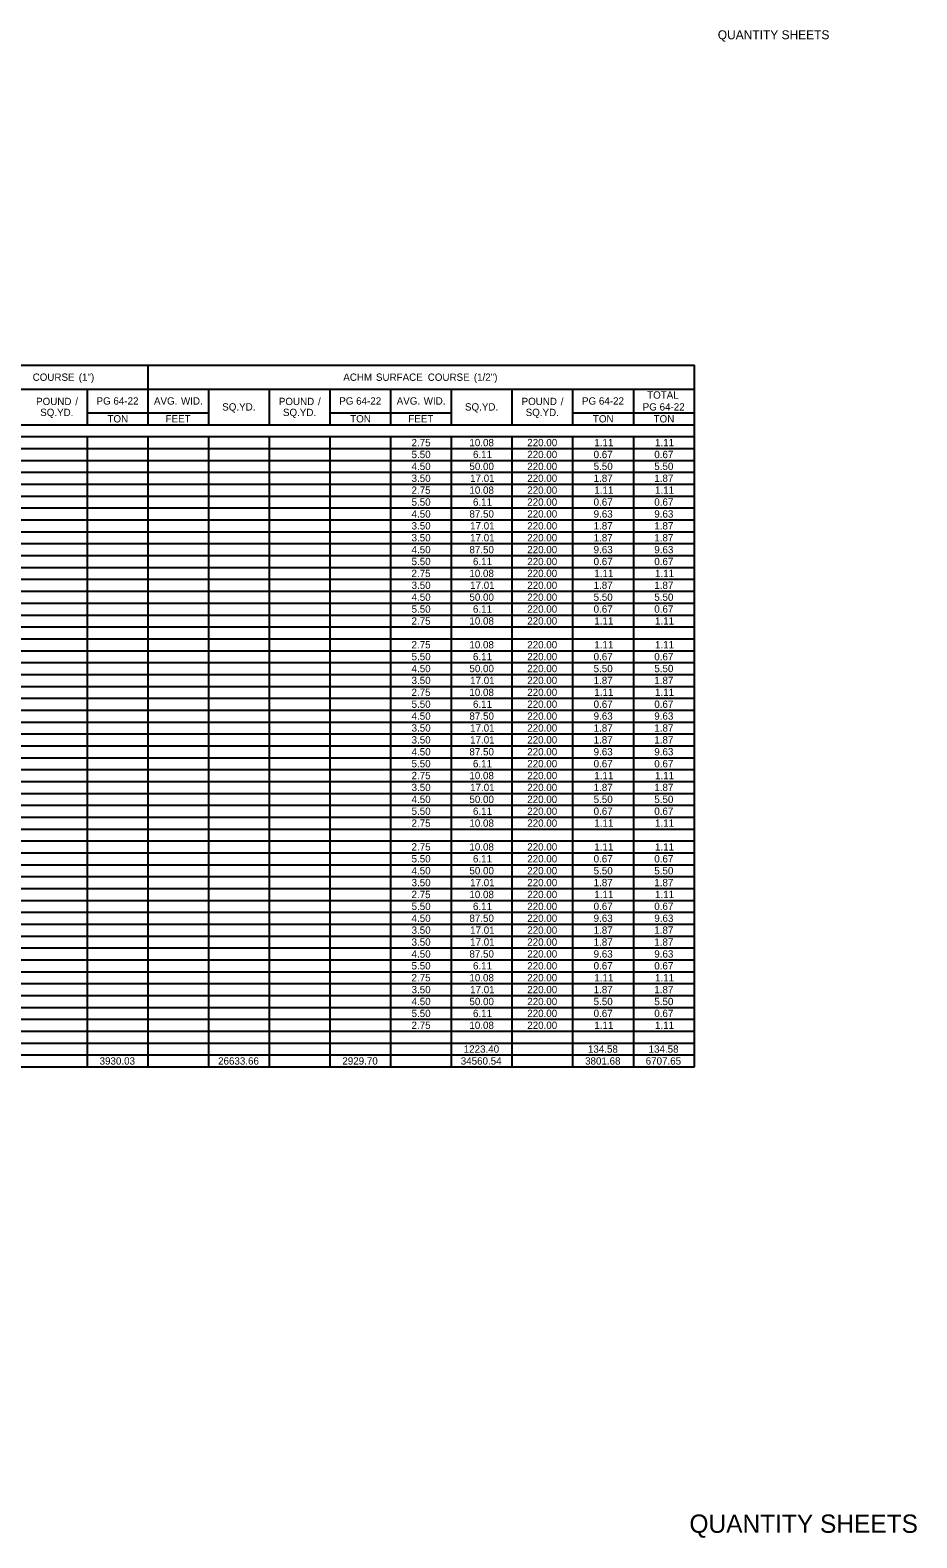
# Model space of a CAD drawing. Extents: x 977434 to 989596, y 1525697 to 1528336.
# Drawn here: x 985434 to 986015, y 1527332 to 1528321 of the extents above; entities that cross this region are included whole.
import ezdxf

# ---------------------------------------------------------------- set-up
doc = ezdxf.new("R2010")
doc.units = 0
for name, color, linetype in [('Default', 7, 'Continuous'), ('R_Border', 7, 'Continuous'), ('R_Border Prem', 7, 'Continuous')]:
    doc.layers.add(name, color=color, linetype=linetype)

msp = doc.modelspace()

# ---------------------------------------------------------------- linework, layer by layer
at = {"layer": 'Default'}
for p, q in [((984511.57, 1528101.06), (985869.55, 1528101.06)), ((985511.53, 1528085.46), (985511.53, 1528101.06)), ((985511.53, 1528062.06), (985511.53, 1528101.06)), ((985869.55, 1527656.46), (985869.55, 1528101.06)), ((985869.55, 1527640.86), (985869.55, 1528101.06)), ((984835.27, 1528085.46), (985869.55, 1528085.46)), ((985471.75, 1528062.06), (985471.75, 1528085.46)), ((985551.31, 1528085.46), (985591.09, 1528085.46)), ((985551.31, 1528062.06), (985551.31, 1528085.46)), ((985591.09, 1528062.06), (985591.09, 1528085.46)), ((985630.87, 1528062.06), (985630.87, 1528085.46)), ((985670.65, 1528062.06), (985670.65, 1528085.46)), ((985710.43, 1528085.46), (985750.21, 1528085.46)), ((985710.43, 1528062.06), (985710.43, 1528085.46)), ((985750.21, 1528062.06), (985750.21, 1528085.46)), ((985789.99, 1528062.06), (985789.99, 1528085.46)), ((985829.77, 1528062.06), (985829.77, 1528085.46)), ((984511.57, 1528062.06), (985869.55, 1528062.06)), ((985392.19, 1528062.06), (985551.31, 1528062.06)), ((985471.75, 1528069.86), (985551.31, 1528069.86)), ((985511.53, 1528062.06), (985511.53, 1528069.86)), ((985551.31, 1528062.06), (985551.31, 1528069.86)), ((985551.31, 1528062.06), (985710.43, 1528062.06)), ((985630.87, 1528069.86), (985710.43, 1528069.86)), ((985670.65, 1528062.06), (985670.65, 1528069.86)), ((985710.43, 1528062.06), (985710.43, 1528069.86)), ((985710.43, 1528062.06), (985869.55, 1528062.06)), ((985789.99, 1528069.86), (985869.55, 1528069.86)), ((984511.57, 1528054.26), (985869.55, 1528054.26)), ((985471.75, 1527640.86), (985471.75, 1528054.26)), ((985471.75, 1527640.86), (985471.75, 1528054.26)), ((985511.53, 1527640.86), (985511.53, 1528054.26)), ((985511.53, 1527640.86), (985511.53, 1528054.26)), ((985551.31, 1527640.86), (985551.31, 1528054.26)), ((985551.31, 1527640.86), (985551.31, 1528054.26)), ((985591.09, 1527664.26), (985591.09, 1528054.26)), ((985591.09, 1527640.86), (985591.09, 1528054.26)), ((985630.87, 1527640.86), (985630.87, 1528054.26)), ((985630.87, 1527640.86), (985630.87, 1528054.26)), ((985670.65, 1527656.46), (985670.65, 1528054.26)), ((985670.65, 1527640.86), (985670.65, 1528054.26)), ((985710.43, 1527640.86), (985710.43, 1528054.26)), ((985710.43, 1527640.86), (985710.43, 1528054.26)), ((985750.21, 1527640.86), (985750.21, 1528054.26)), ((985750.21, 1527640.86), (985750.21, 1528054.26)), ((985789.99, 1527640.86), (985789.99, 1528054.26)), ((985789.99, 1527640.86), (985789.99, 1528054.26)), ((985829.77, 1527640.86), (985829.77, 1528054.26)), ((985829.77, 1527640.86), (985829.77, 1528054.26)), ((984511.57, 1528046.46), (985869.55, 1528046.46)), ((984511.57, 1528038.66), (985869.55, 1528038.66)), ((984511.57, 1528030.86), (985869.55, 1528030.86)), ((984511.57, 1528023.06), (985869.55, 1528023.06)), ((984511.57, 1528015.26), (985869.55, 1528015.26)), ((984511.57, 1528007.46), (985869.55, 1528007.46)), ((984511.57, 1527999.66), (985869.55, 1527999.66)), ((984511.57, 1527991.86), (985869.55, 1527991.86)), ((984511.57, 1527984.06), (985869.55, 1527984.06)), ((984511.57, 1527976.26), (985869.55, 1527976.26)), ((984511.57, 1527968.46), (985869.55, 1527968.46)), ((984511.57, 1527960.66), (985869.55, 1527960.66)), ((984511.57, 1527952.86), (985869.55, 1527952.86)), ((984511.57, 1527945.06), (985869.55, 1527945.06)), ((984511.57, 1527937.26), (985869.55, 1527937.26)), ((984511.57, 1527929.46), (985869.55, 1527929.46)), ((984511.57, 1527921.66), (985869.55, 1527921.66)), ((984511.57, 1527913.86), (985869.55, 1527913.86)), ((984511.57, 1527906.06), (985869.55, 1527906.06)), ((984511.57, 1527898.26), (985869.55, 1527898.26)), ((984511.57, 1527890.46), (985869.55, 1527890.46)), ((984511.57, 1527882.66), (985869.55, 1527882.66)), ((984511.57, 1527874.86), (985869.55, 1527874.86)), ((984511.57, 1527867.06), (985869.55, 1527867.06)), ((984511.57, 1527859.26), (985869.55, 1527859.26)), ((984511.57, 1527851.46), (985869.55, 1527851.46)), ((984511.57, 1527843.66), (985869.55, 1527843.66)), ((984511.57, 1527835.86), (985869.55, 1527835.86)), ((984511.57, 1527828.06), (985869.55, 1527828.06)), ((984511.57, 1527820.26), (985869.55, 1527820.26)), ((984511.57, 1527812.46), (985869.55, 1527812.46)), ((984511.57, 1527804.66), (985869.55, 1527804.66)), ((984511.57, 1527796.86), (985869.55, 1527796.86)), ((984511.57, 1527789.06), (985869.55, 1527789.06)), ((984511.57, 1527781.26), (985869.55, 1527781.26)), ((984511.57, 1527773.46), (985869.55, 1527773.46)), ((984511.57, 1527765.66), (985869.55, 1527765.66)), ((984511.57, 1527757.86), (985869.55, 1527757.86)), ((984511.57, 1527750.06), (985869.55, 1527750.06)), ((984511.57, 1527742.26), (985869.55, 1527742.26)), ((984511.57, 1527734.46), (985869.55, 1527734.46)), ((984511.57, 1527726.66), (985869.55, 1527726.66)), ((984511.57, 1527718.86), (985869.55, 1527718.86)), ((984511.57, 1527711.06), (985869.55, 1527711.06)), ((984511.57, 1527703.26), (985869.55, 1527703.26)), ((984511.57, 1527695.46), (985869.55, 1527695.46)), ((984511.57, 1527687.66), (985869.55, 1527687.66)), ((984511.57, 1527679.86), (985869.55, 1527679.86)), ((984511.57, 1527672.06), (985869.55, 1527672.06)), ((984511.57, 1527664.26), (985869.55, 1527664.26)), ((984511.57, 1527656.46), (985869.55, 1527656.46)), ((984511.57, 1527648.66), (985869.55, 1527648.66)), ((985591.09, 1527640.86), (985591.09, 1527656.46)), ((985630.87, 1527656.46), (985670.65, 1527656.46)), ((985670.65, 1527656.46), (985829.77, 1527656.46)), ((985670.65, 1527640.86), (985670.65, 1527648.66)), ((985829.77, 1527656.46), (985869.55, 1527656.46)), ((985869.55, 1527640.86), (985869.55, 1527648.66)), ((984511.57, 1527640.86), (985869.55, 1527640.86))]:
    msp.add_line(p, q, dxfattribs=at)

# ---------------------------------------------------------------- texts
for s, p in [(' COURSE', (985434.01, 1528090.86)), (' (1")', (985464.23, 1528090.86)), ('ACHM', (985639.4, 1528090.86)), (' SURFACE', (985659.04, 1528090.86)), (' COURSE', (985692.99, 1528090.86)), (' (1/2")', (985723.21, 1528090.86)), ('TOTAL', (985838.59, 1528079.16)), ('POUND', (985438.05, 1528074.96)), ('SQ.YD.', (985440.73, 1528067.76)), (' /', (985461.94, 1528074.96)), ('PG', (985477.66, 1528075.26)), (' 64-22', (985486.95, 1528075.26)), ('AVG.', (985515.3, 1528075.26)), (' WID.', (985531.24, 1528075.26)), ('SQ.YD.', (985560.07, 1528071.36)), ('POUND', (985597.17, 1528074.96)), ('SQ.YD.', (985599.85, 1528067.76)), (' /', (985621.06, 1528074.96)), ('PG', (985636.78, 1528075.26)), (' 64-22', (985646.07, 1528075.26)), ('AVG.', (985674.42, 1528075.26)), (' WID.', (985690.36, 1528075.26)), ('SQ.YD.', (985719.19, 1528071.36)), ('POUND', (985756.29, 1528074.96)), ('SQ.YD.', (985758.97, 1528067.76)), (' /', (985780.18, 1528074.96)), ('PG', (985795.9, 1528075.26)), (' 64-22', (985805.19, 1528075.26)), ('PG', (985835.68, 1528071.36)), (' 64-22', (985844.97, 1528071.36)), ('TON', (985484.83, 1528063.56)), ('FEET', (985522.92, 1528063.56)), ('TON', (985643.95, 1528063.56)), ('FEET', (985682.04, 1528063.56)), ('TON', (985803.07, 1528063.56)), ('TON', (985842.85, 1528063.56)), ('2.75', (985684.15, 1528047.96)), ('10.08', (985722.08, 1528047.96)), ('220.00', (985760.01, 1528047.96)), ('1.11', (985803.98, 1528047.96)), ('1.11', (985843.76, 1528047.96)), ('5.50', (985684.18, 1528040.16)), ('6.11', (985724.42, 1528040.16)), ('220.00', (985760.01, 1528040.16)), ('0.67', (985803.51, 1528040.16)), ('0.67', (985843.29, 1528040.16)), ('4.50', (985684.18, 1528032.36)), ('50.00', (985722.1, 1528032.36)), ('220.00', (985760.01, 1528032.36)), ('5.50', (985803.52, 1528032.36)), ('5.50', (985843.3, 1528032.36)), ('3.50', (985684.18, 1528024.56)), ('17.01', (985722.55, 1528024.56)), ('220.00', (985760.01, 1528024.56)), ('1.87', (985803.51, 1528024.56)), ('1.87', (985843.29, 1528024.56)), ('5.50', (985684.18, 1528008.96)), ('2.75', (985684.15, 1528016.76)), ('10.08', (985722.08, 1528016.76)), ('6.11', (985724.42, 1528008.96)), ('220.00', (985760.01, 1528016.76)), ('220.00', (985760.01, 1528008.96)), ('0.67', (985803.51, 1528008.96)), ('1.11', (985803.98, 1528016.76)), ('0.67', (985843.29, 1528008.96)), ('1.11', (985843.76, 1528016.76)), ('4.50', (985684.18, 1528001.16)), ('87.50', (985722.1, 1528001.16)), ('220.00', (985760.01, 1528001.16)), ('9.63', (985803.51, 1528001.16)), ('9.63', (985843.29, 1528001.16)), ('3.50', (985684.18, 1527993.36)), ('17.01', (985722.55, 1527993.36)), ('220.00', (985760.01, 1527993.36)), ('1.87', (985803.51, 1527993.36)), ('1.87', (985843.29, 1527993.36)), ('3.50', (985684.18, 1527985.56)), ('17.01', (985722.55, 1527985.56)), ('220.00', (985760.01, 1527985.56)), ('1.87', (985803.51, 1527985.56)), ('1.87', (985843.29, 1527985.56)), ('4.50', (985684.18, 1527977.76)), ('5.50', (985684.18, 1527969.96)), ('87.50', (985722.1, 1527977.76)), ('6.11', (985724.42, 1527969.96)), ('220.00', (985760.01, 1527977.76)), ('220.00', (985760.01, 1527969.96)), ('0.67', (985803.51, 1527969.96)), ('9.63', (985803.51, 1527977.76)), ('0.67', (985843.29, 1527969.96)), ('9.63', (985843.29, 1527977.76)), ('2.75', (985684.15, 1527962.16)), ('10.08', (985722.08, 1527962.16)), ('220.00', (985760.01, 1527962.16)), ('1.11', (985803.98, 1527962.16)), ('1.11', (985843.76, 1527962.16)), ('3.50', (985684.18, 1527954.36)), ('17.01', (985722.55, 1527954.36)), ('220.00', (985760.01, 1527954.36)), ('1.87', (985803.51, 1527954.36)), ('1.87', (985843.29, 1527954.36)), ('4.50', (985684.18, 1527946.56)), ('5.50', (985684.18, 1527938.76)), ('50.00', (985722.1, 1527946.56)), ('6.11', (985724.42, 1527938.76)), ('220.00', (985760.01, 1527946.56)), ('220.00', (985760.01, 1527938.76)), ('0.67', (985803.51, 1527938.76)), ('5.50', (985803.52, 1527946.56)), ('0.67', (985843.29, 1527938.76)), ('5.50', (985843.3, 1527946.56)), ('2.75', (985684.15, 1527930.96)), ('10.08', (985722.08, 1527930.96)), ('220.00', (985760.01, 1527930.96)), ('1.11', (985803.98, 1527930.96)), ('1.11', (985843.76, 1527930.96)), ('2.75', (985684.15, 1527915.36)), ('10.08', (985722.08, 1527915.36)), ('220.00', (985760.01, 1527915.36)), ('1.11', (985803.98, 1527915.36)), ('1.11', (985843.76, 1527915.36)), ('4.50', (985684.18, 1527899.76)), ('5.50', (985684.18, 1527907.56)), ('50.00', (985722.1, 1527899.76)), ('6.11', (985724.42, 1527907.56)), ('220.00', (985760.01, 1527907.56)), ('220.00', (985760.01, 1527899.76)), ('0.67', (985803.51, 1527907.56)), ('5.50', (985803.52, 1527899.76)), ('0.67', (985843.29, 1527907.56)), ('5.50', (985843.3, 1527899.76)), ('3.50', (985684.18, 1527891.96)), ('17.01', (985722.55, 1527891.96)), ('220.00', (985760.01, 1527891.96)), ('1.87', (985803.51, 1527891.96)), ('1.87', (985843.29, 1527891.96)), ('2.75', (985684.15, 1527884.16)), ('10.08', (985722.08, 1527884.16)), ('220.00', (985760.01, 1527884.16)), ('1.11', (985803.98, 1527884.16)), ('1.11', (985843.76, 1527884.16)), ('5.50', (985684.18, 1527876.36)), ('6.11', (985724.42, 1527876.36)), ('220.00', (985760.01, 1527876.36)), ('0.67', (985803.51, 1527876.36)), ('0.67', (985843.29, 1527876.36)), ('4.50', (985684.18, 1527868.56)), ('3.50', (985684.18, 1527860.76)), ('87.50', (985722.1, 1527868.56)), ('17.01', (985722.55, 1527860.76)), ('220.00', (985760.01, 1527868.56)), ('220.00', (985760.01, 1527860.76)), ('9.63', (985803.51, 1527868.56)), ('1.87', (985803.51, 1527860.76)), ('9.63', (985843.29, 1527868.56)), ('1.87', (985843.29, 1527860.76)), ('3.50', (985684.18, 1527852.96)), ('17.01', (985722.55, 1527852.96)), ('220.00', (985760.01, 1527852.96)), ('1.87', (985803.51, 1527852.96)), ('1.87', (985843.29, 1527852.96)), ('4.50', (985684.18, 1527845.16)), ('87.50', (985722.1, 1527845.16)), ('220.00', (985760.01, 1527845.16)), ('9.63', (985803.51, 1527845.16)), ('9.63', (985843.29, 1527845.16)), ('5.50', (985684.18, 1527837.36)), ('6.11', (985724.42, 1527837.36)), ('220.00', (985760.01, 1527837.36)), ('0.67', (985803.51, 1527837.36)), ('0.67', (985843.29, 1527837.36)), ('3.50', (985684.18, 1527821.76)), ('2.75', (985684.15, 1527829.56)), ('10.08', (985722.08, 1527829.56)), ('17.01', (985722.55, 1527821.76)), ('220.00', (985760.01, 1527829.56)), ('220.00', (985760.01, 1527821.76)), ('1.87', (985803.51, 1527821.76)), ('1.11', (985803.98, 1527829.56)), ('1.87', (985843.29, 1527821.76)), ('1.11', (985843.76, 1527829.56)), ('4.50', (985684.18, 1527813.96)), ('50.00', (985722.1, 1527813.96)), ('220.00', (985760.01, 1527813.96)), ('5.50', (985803.52, 1527813.96)), ('5.50', (985843.3, 1527813.96)), ('5.50', (985684.18, 1527806.16)), ('6.11', (985724.42, 1527806.16)), ('220.00', (985760.01, 1527806.16)), ('0.67', (985803.51, 1527806.16)), ('0.67', (985843.29, 1527806.16)), ('2.75', (985684.15, 1527798.36)), ('10.08', (985722.08, 1527798.36)), ('220.00', (985760.01, 1527798.36)), ('1.11', (985803.98, 1527798.36)), ('1.11', (985843.76, 1527798.36)), ('2.75', (985684.15, 1527782.76)), ('10.08', (985722.08, 1527782.76)), ('220.00', (985760.01, 1527782.76)), ('1.11', (985803.98, 1527782.76)), ('1.11', (985843.76, 1527782.76)), ('5.50', (985684.18, 1527774.96)), ('6.11', (985724.42, 1527774.96)), ('220.00', (985760.01, 1527774.96)), ('0.67', (985803.51, 1527774.96)), ('0.67', (985843.29, 1527774.96)), ('4.50', (985684.18, 1527767.16)), ('50.00', (985722.1, 1527767.16)), ('220.00', (985760.01, 1527767.16)), ('5.50', (985803.52, 1527767.16)), ('5.50', (985843.3, 1527767.16)), ('3.50', (985684.18, 1527759.36)), ('2.75', (985684.15, 1527751.56)), ('10.08', (985722.08, 1527751.56)), ('17.01', (985722.55, 1527759.36)), ('220.00', (985760.01, 1527759.36)), ('220.00', (985760.01, 1527751.56)), ('1.87', (985803.51, 1527759.36)), ('1.11', (985803.98, 1527751.56)), ('1.87', (985843.29, 1527759.36)), ('1.11', (985843.76, 1527751.56)), ('5.50', (985684.18, 1527743.76)), ('6.11', (985724.42, 1527743.76)), ('220.00', (985760.01, 1527743.76)), ('0.67', (985803.51, 1527743.76)), ('0.67', (985843.29, 1527743.76)), ('4.50', (985684.18, 1527735.96)), ('87.50', (985722.1, 1527735.96)), ('220.00', (985760.01, 1527735.96)), ('9.63', (985803.51, 1527735.96)), ('9.63', (985843.29, 1527735.96)), ('3.50', (985684.18, 1527728.16)), ('17.01', (985722.55, 1527728.16)), ('220.00', (985760.01, 1527728.16)), ('1.87', (985803.51, 1527728.16)), ('1.87', (985843.29, 1527728.16)), ('4.50', (985684.18, 1527712.56)), ('3.50', (985684.18, 1527720.36)), ('87.50', (985722.1, 1527712.56)), ('17.01', (985722.55, 1527720.36)), ('220.00', (985760.01, 1527720.36)), ('220.00', (985760.01, 1527712.56)), ('9.63', (985803.51, 1527712.56)), ('1.87', (985803.51, 1527720.36)), ('9.63', (985843.29, 1527712.56)), ('1.87', (985843.29, 1527720.36)), ('5.50', (985684.18, 1527704.76)), ('6.11', (985724.42, 1527704.76)), ('220.00', (985760.01, 1527704.76)), ('0.67', (985803.51, 1527704.76)), ('0.67', (985843.29, 1527704.76)), ('2.75', (985684.15, 1527696.96)), ('10.08', (985722.08, 1527696.96)), ('220.00', (985760.01, 1527696.96)), ('1.11', (985803.98, 1527696.96)), ('1.11', (985843.76, 1527696.96)), ('4.50', (985684.18, 1527681.36)), ('3.50', (985684.18, 1527689.16)), ('50.00', (985722.1, 1527681.36)), ('17.01', (985722.55, 1527689.16)), ('220.00', (985760.01, 1527689.16)), ('220.00', (985760.01, 1527681.36)), ('5.50', (985803.52, 1527681.36)), ('1.87', (985803.51, 1527689.16)), ('5.50', (985843.3, 1527681.36)), ('1.87', (985843.29, 1527689.16)), ('5.50', (985684.18, 1527673.56)), ('6.11', (985724.42, 1527673.56)), ('220.00', (985760.01, 1527673.56)), ('0.67', (985803.51, 1527673.56)), ('0.67', (985843.29, 1527673.56)), ('2.75', (985684.15, 1527665.76)), ('10.08', (985722.08, 1527665.76)), ('220.00', (985760.01, 1527665.76)), ('1.11', (985803.98, 1527665.76)), ('1.11', (985843.76, 1527665.76)), ('3930.03', (985479.67, 1527642.36)), ('26633.66', (985557.34, 1527642.36)), ('2929.70', (985638.81, 1527642.36)), ('34560.54', (985716.42, 1527642.36)), ('1223.40', (985718.37, 1527650.16)), ('3801.68', (985797.92, 1527642.36)), ('134.58', (985799.78, 1527650.16)), ('6707.65', (985837.65, 1527642.36)), ('134.58', (985839.56, 1527650.16))]:
    msp.add_text(s, height=4.8, dxfattribs=at).set_placement(p)
at = {"layer": 'R_Border'}
msp.add_text('QUANTITY SHEETS', height=12, rotation=360, dxfattribs=at).set_placement((985866.33, 1527335.24))
at = {"layer": 'R_Border Prem'}
msp.add_text('QUANTITY SHEETS', height=5.862, rotation=360, dxfattribs=at).set_placement((985884.91, 1528314.92))

doc.saveas('drawing.dxf')
